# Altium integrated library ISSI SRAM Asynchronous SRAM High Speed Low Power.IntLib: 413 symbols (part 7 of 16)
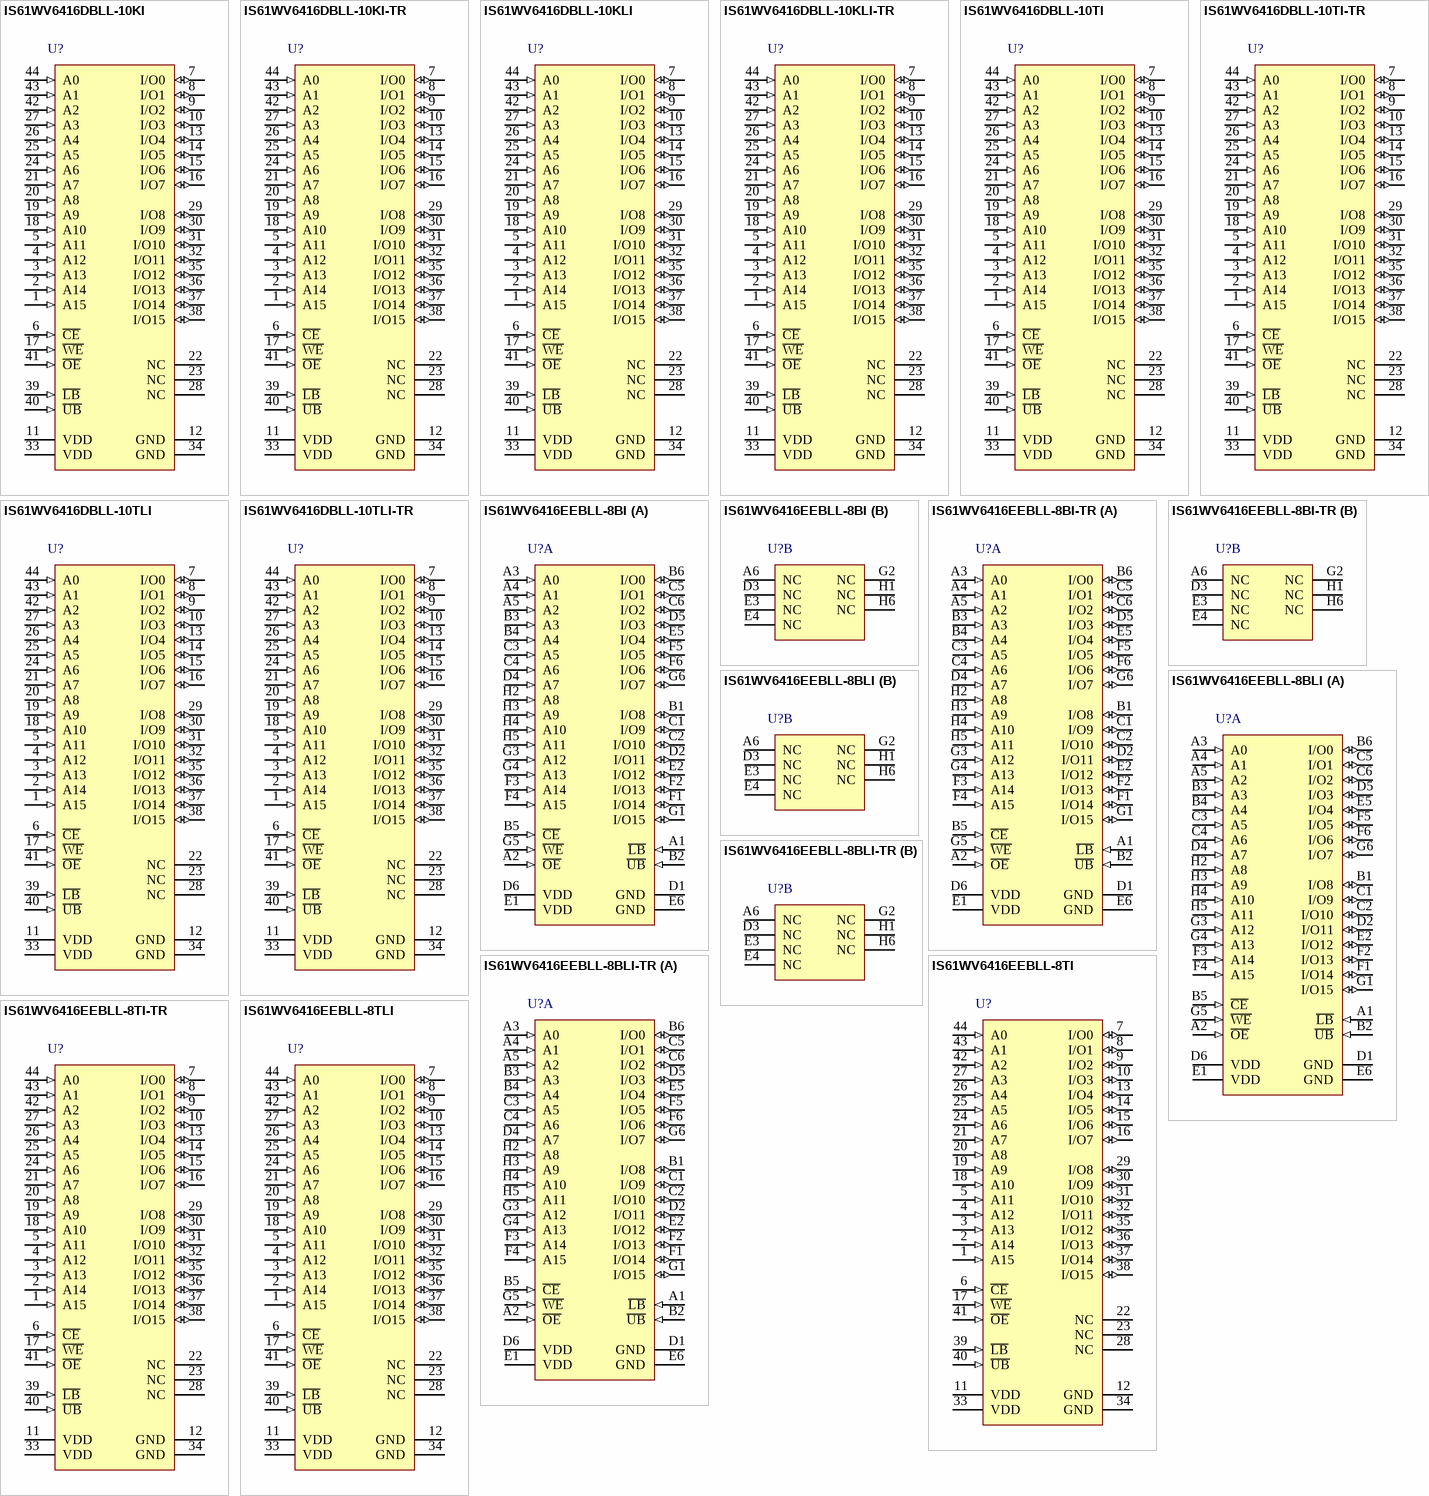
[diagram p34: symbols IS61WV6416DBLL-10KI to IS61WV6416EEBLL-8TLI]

## IS61WV6416EEBLL-8TLI
designator U?
1 M High Speed Asynchronous CMOS SRAM with ECC, 64 K x 16, -40 to 85 degC, 44-Pin SOP (TSOP-2-44), Pb-Free; Manufacturer: Integrated Silicon Solution Inc (ISSI); PartNumber: IS61WV6416EEBLL-8TLI; Density: 1M; Organization: 64K x 16; Packing: Tray / Tube; Speed (ns): 8
footprint ISSI-TSOP-2-44_N (SOP, 44-Leads, Body 18.5x10.3mm, Pitch 0.8mm, IPC Medium Density)
pins: 1 A15 (in) "Address Inputs", 2 A14 (in) "Address Inputs", 3 A13 (in) "Address Inputs", 4 A12 (in) "Address Inputs", 5 A11 (in) "Address Inputs", 6 ~{CE} (in) "Chip Enable Input", 7 I/O0 (io) "Data Inputs/Outputs", 8 I/O1 (io) "Data Inputs/Outputs", 9 I/O2 (io) "Data Inputs/Outputs", 10 I/O3 (io) "Data Inputs/Outputs", 11 VDD (power) "Power", 12 GND (power) "Ground", 13 I/O4 (io) "Data Inputs/Outputs", 14 I/O5 (io) "Data Inputs/Outputs", 15 I/O6 (io) "Data Inputs/Outputs", 16 I/O7 (io) "Data Inputs/Outputs", 17 ~{WE} (in) "Write Enable Input", 18 A10 (in) "Address Inputs", 19 A9 (in) "Address Inputs", 20 A8 (in) "Address Inputs", 21 A7 (in) "Address Inputs", 22 NC "No Connection", 23 NC "No Connection", 24 A6 (in) "Address Inputs", 25 A5 (in) "Address Inputs", 26 A4 (in) "Address Inputs", 27 A3 (in) "Address Inputs", 28 NC "No Connection", 29 I/O8 (io) "Data Inputs/Outputs", 30 I/O9 (io) "Data Inputs/Outputs", 31 I/O10 (io) "Data Inputs/Outputs", 32 I/O11 (io) "Data Inputs/Outputs", 33 VDD (power) "Power", 34 GND (power) "Ground", 35 I/O12 (io) "Data Inputs/Outputs", 36 I/O13 (io) "Data Inputs/Outputs", 37 I/O14 (io) "Data Inputs/Outputs", 38 I/O15 (io) "Data Inputs/Outputs", 39 ~{LB} (in) "Lower-byte Control (I/O0-I/O7)", 40 ~{UB} (in) "Upper-byte Control (I/O8-I/O15)", 41 ~{OE} (in) "Output Enable Input", 42 A2 (in) "Address Inputs", 43 A1 (in) "Address Inputs", 44 A0 (in) "Address Inputs"

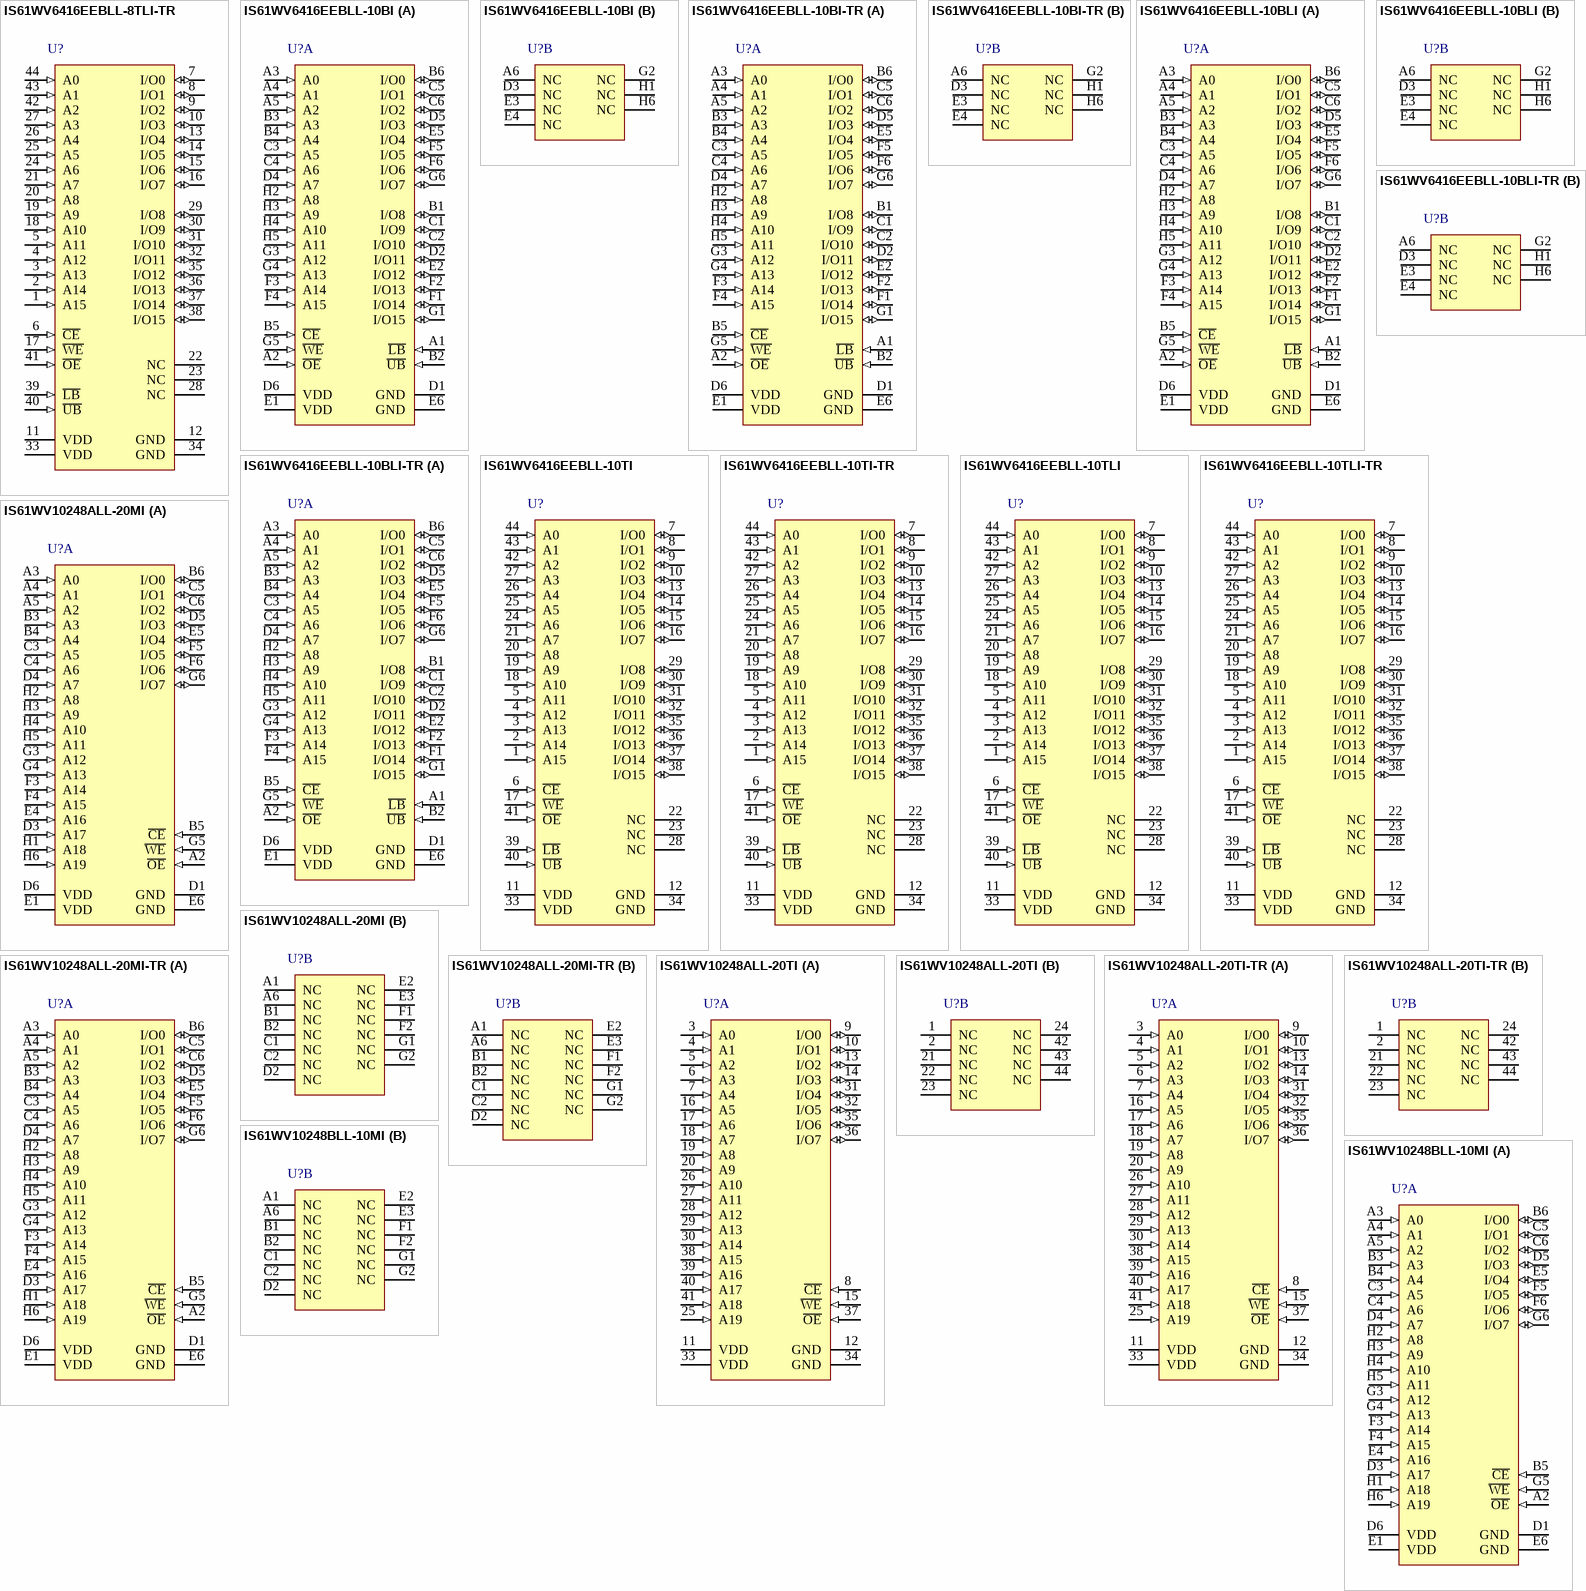
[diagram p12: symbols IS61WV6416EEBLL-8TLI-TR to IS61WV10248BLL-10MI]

## IS61WV6416EEBLL-8TLI-TR
designator U?
1 M High Speed Asynchronous CMOS SRAM with ECC, 64 K x 16, -40 to 85 degC, 44-Pin SOP (TSOP-2-44), Pb-Free; Manufacturer: Integrated Silicon Solution Inc (ISSI); PartNumber: IS61WV6416EEBLL-8TLI-TR; Density: 1M; Organization: 64K x 16; Packing: Tape & Reel; Speed (ns): 8
footprint ISSI-TSOP-2-44_N (SOP, 44-Leads, Body 18.5x10.3mm, Pitch 0.8mm, IPC Medium Density)
pins: 1 A15 (in) "Address Inputs", 2 A14 (in) "Address Inputs", 3 A13 (in) "Address Inputs", 4 A12 (in) "Address Inputs", 5 A11 (in) "Address Inputs", 6 ~{CE} (in) "Chip Enable Input", 7 I/O0 (io) "Data Inputs/Outputs", 8 I/O1 (io) "Data Inputs/Outputs", 9 I/O2 (io) "Data Inputs/Outputs", 10 I/O3 (io) "Data Inputs/Outputs", 11 VDD (power) "Power", 12 GND (power) "Ground", 13 I/O4 (io) "Data Inputs/Outputs", 14 I/O5 (io) "Data Inputs/Outputs", 15 I/O6 (io) "Data Inputs/Outputs", 16 I/O7 (io) "Data Inputs/Outputs", 17 ~{WE} (in) "Write Enable Input", 18 A10 (in) "Address Inputs", 19 A9 (in) "Address Inputs", 20 A8 (in) "Address Inputs", 21 A7 (in) "Address Inputs", 22 NC "No Connection", 23 NC "No Connection", 24 A6 (in) "Address Inputs", 25 A5 (in) "Address Inputs", 26 A4 (in) "Address Inputs", 27 A3 (in) "Address Inputs", 28 NC "No Connection", 29 I/O8 (io) "Data Inputs/Outputs", 30 I/O9 (io) "Data Inputs/Outputs", 31 I/O10 (io) "Data Inputs/Outputs", 32 I/O11 (io) "Data Inputs/Outputs", 33 VDD (power) "Power", 34 GND (power) "Ground", 35 I/O12 (io) "Data Inputs/Outputs", 36 I/O13 (io) "Data Inputs/Outputs", 37 I/O14 (io) "Data Inputs/Outputs", 38 I/O15 (io) "Data Inputs/Outputs", 39 ~{LB} (in) "Lower-byte Control (I/O0-I/O7)", 40 ~{UB} (in) "Upper-byte Control (I/O8-I/O15)", 41 ~{OE} (in) "Output Enable Input", 42 A2 (in) "Address Inputs", 43 A1 (in) "Address Inputs", 44 A0 (in) "Address Inputs"

## IS61WV6416EEBLL-10BI
designator U?
1 M High Speed Asynchronous CMOS SRAM with ECC, 64 K x 16, -40 to 85 degC, 48-Pin BGA (TF-BGA-48); Manufacturer: Integrated Silicon Solution Inc (ISSI); PartNumber: IS61WV6416EEBLL-10BI; Density: 1M; Organization: 64K x 16; Packing: Tray / Tube; Speed (ns): 10
footprint ISSI-TF-BGA-48-6000X8000DE (BGA, 48-Balls, Body 8x6mm, Pitch 0.75mm)
part A pins: A1 ~{LB} (in) "Lower-byte Control (I/O0-I/O7)", A2 ~{OE} (in) "Output Enable Input", A3 A0 (in) "Address Input", A4 A1 (in) "Address Input", A5 A2 (in) "Address Input", B1 I/O8 (io) "Data Input/Output", B2 ~{UB} (in) "Upper-byte Control (I/O8-I/O15)", B3 A3 (in) "Address Input", B4 A4 (in) "Address Input", B5 ~{CE} (in) "Chip Enable Input", B6 I/O0 (io) "Data Input/Output", C1 I/O9 (io) "Data Input/Output", C2 I/O10 (io) "Data Input/Output", C3 A5 (in) "Address Input", C4 A6 (in) "Address Input", C5 I/O1 (io) "Data Input/Output", C6 I/O2 (io) "Data Input/Output", D1 GND (power) "Ground", D2 I/O11 (io) "Data Input/Output", D4 A7 (in) "Address Input", D5 I/O3 (io) "Data Input/Output", D6 VDD (power) "Power", E1 VDD (power) "Power", E2 I/O12 (io) "Data Input/Output", E5 I/O4 (io) "Data Input/Output", E6 GND (power) "Ground", F1 I/O14 (io) "Data Input/Output", F2 I/O13 (io) "Data Input/Output", F3 A14 (in) "Address Input", F4 A15 (in) "Address Input", F5 I/O5 (io) "Data Input/Output", F6 I/O6 (io) "Data Input/Output", G1 I/O15 (io) "Data Input/Output", G3 A12 (in) "Address Input", G4 A13 (in) "Address Input", G5 ~{WE} (in) "Write Enable Input", G6 I/O7 (io) "Data Input/Output", H2 A8 (in) "Address Input", H3 A9 (in) "Address Input", H4 A10 (in) "Address Input", H5 A11 (in) "Address Input"
part B pins: A6 NC "No Connection", D3 NC "No Connection", E3 NC "No Connection", E4 NC "No Connection", G2 NC "No Connection", H1 NC "No Connection", H6 NC "No Connection"

## IS61WV6416EEBLL-10BI-TR
designator U?
1 M High Speed Asynchronous CMOS SRAM with ECC, 64 K x 16, -40 to 85 degC, 48-Pin BGA (TF-BGA-48); Manufacturer: Integrated Silicon Solution Inc (ISSI); PartNumber: IS61WV6416EEBLL-10BI-TR; Density: 1M; Organization: 64K x 16; Packing: Tape & Reel; Speed (ns): 10
footprint ISSI-TF-BGA-48-6000X8000DE (BGA, 48-Balls, Body 8x6mm, Pitch 0.75mm)
part A pins: A1 ~{LB} (in) "Lower-byte Control (I/O0-I/O7)", A2 ~{OE} (in) "Output Enable Input", A3 A0 (in) "Address Input", A4 A1 (in) "Address Input", A5 A2 (in) "Address Input", B1 I/O8 (io) "Data Input/Output", B2 ~{UB} (in) "Upper-byte Control (I/O8-I/O15)", B3 A3 (in) "Address Input", B4 A4 (in) "Address Input", B5 ~{CE} (in) "Chip Enable Input", B6 I/O0 (io) "Data Input/Output", C1 I/O9 (io) "Data Input/Output", C2 I/O10 (io) "Data Input/Output", C3 A5 (in) "Address Input", C4 A6 (in) "Address Input", C5 I/O1 (io) "Data Input/Output", C6 I/O2 (io) "Data Input/Output", D1 GND (power) "Ground", D2 I/O11 (io) "Data Input/Output", D4 A7 (in) "Address Input", D5 I/O3 (io) "Data Input/Output", D6 VDD (power) "Power", E1 VDD (power) "Power", E2 I/O12 (io) "Data Input/Output", E5 I/O4 (io) "Data Input/Output", E6 GND (power) "Ground", F1 I/O14 (io) "Data Input/Output", F2 I/O13 (io) "Data Input/Output", F3 A14 (in) "Address Input", F4 A15 (in) "Address Input", F5 I/O5 (io) "Data Input/Output", F6 I/O6 (io) "Data Input/Output", G1 I/O15 (io) "Data Input/Output", G3 A12 (in) "Address Input", G4 A13 (in) "Address Input", G5 ~{WE} (in) "Write Enable Input", G6 I/O7 (io) "Data Input/Output", H2 A8 (in) "Address Input", H3 A9 (in) "Address Input", H4 A10 (in) "Address Input", H5 A11 (in) "Address Input"
part B pins: A6 NC "No Connection", D3 NC "No Connection", E3 NC "No Connection", E4 NC "No Connection", G2 NC "No Connection", H1 NC "No Connection", H6 NC "No Connection"

## IS61WV6416EEBLL-10BLI
designator U?
1 M High Speed Asynchronous CMOS SRAM with ECC, 64 K x 16, -40 to 85 degC, 48-Pin BGA (TF-BGA-48), Pb-Free; Manufacturer: Integrated Silicon Solution Inc (ISSI); PartNumber: IS61WV6416EEBLL-10BLI; Density: 1M; Organization: 64K x 16; Packing: Tray / Tube; Speed (ns): 10
footprint ISSI-TF-BGA-48-6000X8000DE (BGA, 48-Balls, Body 8x6mm, Pitch 0.75mm)
part A pins: A1 ~{LB} (in) "Lower-byte Control (I/O0-I/O7)", A2 ~{OE} (in) "Output Enable Input", A3 A0 (in) "Address Input", A4 A1 (in) "Address Input", A5 A2 (in) "Address Input", B1 I/O8 (io) "Data Input/Output", B2 ~{UB} (in) "Upper-byte Control (I/O8-I/O15)", B3 A3 (in) "Address Input", B4 A4 (in) "Address Input", B5 ~{CE} (in) "Chip Enable Input", B6 I/O0 (io) "Data Input/Output", C1 I/O9 (io) "Data Input/Output", C2 I/O10 (io) "Data Input/Output", C3 A5 (in) "Address Input", C4 A6 (in) "Address Input", C5 I/O1 (io) "Data Input/Output", C6 I/O2 (io) "Data Input/Output", D1 GND (power) "Ground", D2 I/O11 (io) "Data Input/Output", D4 A7 (in) "Address Input", D5 I/O3 (io) "Data Input/Output", D6 VDD (power) "Power", E1 VDD (power) "Power", E2 I/O12 (io) "Data Input/Output", E5 I/O4 (io) "Data Input/Output", E6 GND (power) "Ground", F1 I/O14 (io) "Data Input/Output", F2 I/O13 (io) "Data Input/Output", F3 A14 (in) "Address Input", F4 A15 (in) "Address Input", F5 I/O5 (io) "Data Input/Output", F6 I/O6 (io) "Data Input/Output", G1 I/O15 (io) "Data Input/Output", G3 A12 (in) "Address Input", G4 A13 (in) "Address Input", G5 ~{WE} (in) "Write Enable Input", G6 I/O7 (io) "Data Input/Output", H2 A8 (in) "Address Input", H3 A9 (in) "Address Input", H4 A10 (in) "Address Input", H5 A11 (in) "Address Input"
part B pins: A6 NC "No Connection", D3 NC "No Connection", E3 NC "No Connection", E4 NC "No Connection", G2 NC "No Connection", H1 NC "No Connection", H6 NC "No Connection"

## IS61WV6416EEBLL-10BLI-TR
designator U?
1 M High Speed Asynchronous CMOS SRAM with ECC, 64 K x 16, -40 to 85 degC, 48-Pin BGA (TF-BGA-48), Pb-Free; Manufacturer: Integrated Silicon Solution Inc (ISSI); PartNumber: IS61WV6416EEBLL-10BLI-TR; Density: 1M; Organization: 64K x 16; Packing: Tape & Reel; Speed (ns): 10
footprint ISSI-TF-BGA-48-6000X8000DE (BGA, 48-Balls, Body 8x6mm, Pitch 0.75mm)
part A pins: A1 ~{LB} (in) "Lower-byte Control (I/O0-I/O7)", A2 ~{OE} (in) "Output Enable Input", A3 A0 (in) "Address Input", A4 A1 (in) "Address Input", A5 A2 (in) "Address Input", B1 I/O8 (io) "Data Input/Output", B2 ~{UB} (in) "Upper-byte Control (I/O8-I/O15)", B3 A3 (in) "Address Input", B4 A4 (in) "Address Input", B5 ~{CE} (in) "Chip Enable Input", B6 I/O0 (io) "Data Input/Output", C1 I/O9 (io) "Data Input/Output", C2 I/O10 (io) "Data Input/Output", C3 A5 (in) "Address Input", C4 A6 (in) "Address Input", C5 I/O1 (io) "Data Input/Output", C6 I/O2 (io) "Data Input/Output", D1 GND (power) "Ground", D2 I/O11 (io) "Data Input/Output", D4 A7 (in) "Address Input", D5 I/O3 (io) "Data Input/Output", D6 VDD (power) "Power", E1 VDD (power) "Power", E2 I/O12 (io) "Data Input/Output", E5 I/O4 (io) "Data Input/Output", E6 GND (power) "Ground", F1 I/O14 (io) "Data Input/Output", F2 I/O13 (io) "Data Input/Output", F3 A14 (in) "Address Input", F4 A15 (in) "Address Input", F5 I/O5 (io) "Data Input/Output", F6 I/O6 (io) "Data Input/Output", G1 I/O15 (io) "Data Input/Output", G3 A12 (in) "Address Input", G4 A13 (in) "Address Input", G5 ~{WE} (in) "Write Enable Input", G6 I/O7 (io) "Data Input/Output", H2 A8 (in) "Address Input", H3 A9 (in) "Address Input", H4 A10 (in) "Address Input", H5 A11 (in) "Address Input"
part B pins: A6 NC "No Connection", D3 NC "No Connection", E3 NC "No Connection", E4 NC "No Connection", G2 NC "No Connection", H1 NC "No Connection", H6 NC "No Connection"

## IS61WV6416EEBLL-10TI
designator U?
1 M High Speed Asynchronous CMOS SRAM with ECC, 64 K x 16, -40 to 85 degC, 44-Pin SOP (TSOP-2-44); Manufacturer: Integrated Silicon Solution Inc (ISSI); PartNumber: IS61WV6416EEBLL-10TI; Density: 1M; Organization: 64K x 16; Packing: Tray / Tube; Speed (ns): 10
footprint ISSI-TSOP-2-44_N (SOP, 44-Leads, Body 18.5x10.3mm, Pitch 0.8mm, IPC Medium Density)
pins: 1 A15 (in) "Address Inputs", 2 A14 (in) "Address Inputs", 3 A13 (in) "Address Inputs", 4 A12 (in) "Address Inputs", 5 A11 (in) "Address Inputs", 6 ~{CE} (in) "Chip Enable Input", 7 I/O0 (io) "Data Inputs/Outputs", 8 I/O1 (io) "Data Inputs/Outputs", 9 I/O2 (io) "Data Inputs/Outputs", 10 I/O3 (io) "Data Inputs/Outputs", 11 VDD (power) "Power", 12 GND (power) "Ground", 13 I/O4 (io) "Data Inputs/Outputs", 14 I/O5 (io) "Data Inputs/Outputs", 15 I/O6 (io) "Data Inputs/Outputs", 16 I/O7 (io) "Data Inputs/Outputs", 17 ~{WE} (in) "Write Enable Input", 18 A10 (in) "Address Inputs", 19 A9 (in) "Address Inputs", 20 A8 (in) "Address Inputs", 21 A7 (in) "Address Inputs", 22 NC "No Connection", 23 NC "No Connection", 24 A6 (in) "Address Inputs", 25 A5 (in) "Address Inputs", 26 A4 (in) "Address Inputs", 27 A3 (in) "Address Inputs", 28 NC "No Connection", 29 I/O8 (io) "Data Inputs/Outputs", 30 I/O9 (io) "Data Inputs/Outputs", 31 I/O10 (io) "Data Inputs/Outputs", 32 I/O11 (io) "Data Inputs/Outputs", 33 VDD (power) "Power", 34 GND (power) "Ground", 35 I/O12 (io) "Data Inputs/Outputs", 36 I/O13 (io) "Data Inputs/Outputs", 37 I/O14 (io) "Data Inputs/Outputs", 38 I/O15 (io) "Data Inputs/Outputs", 39 ~{LB} (in) "Lower-byte Control (I/O0-I/O7)", 40 ~{UB} (in) "Upper-byte Control (I/O8-I/O15)", 41 ~{OE} (in) "Output Enable Input", 42 A2 (in) "Address Inputs", 43 A1 (in) "Address Inputs", 44 A0 (in) "Address Inputs"

## IS61WV6416EEBLL-10TI-TR
designator U?
1 M High Speed Asynchronous CMOS SRAM with ECC, 64 K x 16, -40 to 85 degC, 44-Pin SOP (TSOP-2-44); Manufacturer: Integrated Silicon Solution Inc (ISSI); PartNumber: IS61WV6416EEBLL-10TI-TR; Density: 1M; Organization: 64K x 16; Packing: Tape & Reel; Speed (ns): 10
footprint ISSI-TSOP-2-44_N (SOP, 44-Leads, Body 18.5x10.3mm, Pitch 0.8mm, IPC Medium Density)
pins: 1 A15 (in) "Address Inputs", 2 A14 (in) "Address Inputs", 3 A13 (in) "Address Inputs", 4 A12 (in) "Address Inputs", 5 A11 (in) "Address Inputs", 6 ~{CE} (in) "Chip Enable Input", 7 I/O0 (io) "Data Inputs/Outputs", 8 I/O1 (io) "Data Inputs/Outputs", 9 I/O2 (io) "Data Inputs/Outputs", 10 I/O3 (io) "Data Inputs/Outputs", 11 VDD (power) "Power", 12 GND (power) "Ground", 13 I/O4 (io) "Data Inputs/Outputs", 14 I/O5 (io) "Data Inputs/Outputs", 15 I/O6 (io) "Data Inputs/Outputs", 16 I/O7 (io) "Data Inputs/Outputs", 17 ~{WE} (in) "Write Enable Input", 18 A10 (in) "Address Inputs", 19 A9 (in) "Address Inputs", 20 A8 (in) "Address Inputs", 21 A7 (in) "Address Inputs", 22 NC "No Connection", 23 NC "No Connection", 24 A6 (in) "Address Inputs", 25 A5 (in) "Address Inputs", 26 A4 (in) "Address Inputs", 27 A3 (in) "Address Inputs", 28 NC "No Connection", 29 I/O8 (io) "Data Inputs/Outputs", 30 I/O9 (io) "Data Inputs/Outputs", 31 I/O10 (io) "Data Inputs/Outputs", 32 I/O11 (io) "Data Inputs/Outputs", 33 VDD (power) "Power", 34 GND (power) "Ground", 35 I/O12 (io) "Data Inputs/Outputs", 36 I/O13 (io) "Data Inputs/Outputs", 37 I/O14 (io) "Data Inputs/Outputs", 38 I/O15 (io) "Data Inputs/Outputs", 39 ~{LB} (in) "Lower-byte Control (I/O0-I/O7)", 40 ~{UB} (in) "Upper-byte Control (I/O8-I/O15)", 41 ~{OE} (in) "Output Enable Input", 42 A2 (in) "Address Inputs", 43 A1 (in) "Address Inputs", 44 A0 (in) "Address Inputs"

## IS61WV6416EEBLL-10TLI
designator U?
1 M High Speed Asynchronous CMOS SRAM with ECC, 64 K x 16, -40 to 85 degC, 44-Pin SOP (TSOP-2-44), Pb-Free; Manufacturer: Integrated Silicon Solution Inc (ISSI); PartNumber: IS61WV6416EEBLL-10TLI; Density: 1M; Organization: 64K x 16; Packing: Tray / Tube; Speed (ns): 10
footprint ISSI-TSOP-2-44_N (SOP, 44-Leads, Body 18.5x10.3mm, Pitch 0.8mm, IPC Medium Density)
pins: 1 A15 (in) "Address Inputs", 2 A14 (in) "Address Inputs", 3 A13 (in) "Address Inputs", 4 A12 (in) "Address Inputs", 5 A11 (in) "Address Inputs", 6 ~{CE} (in) "Chip Enable Input", 7 I/O0 (io) "Data Inputs/Outputs", 8 I/O1 (io) "Data Inputs/Outputs", 9 I/O2 (io) "Data Inputs/Outputs", 10 I/O3 (io) "Data Inputs/Outputs", 11 VDD (power) "Power", 12 GND (power) "Ground", 13 I/O4 (io) "Data Inputs/Outputs", 14 I/O5 (io) "Data Inputs/Outputs", 15 I/O6 (io) "Data Inputs/Outputs", 16 I/O7 (io) "Data Inputs/Outputs", 17 ~{WE} (in) "Write Enable Input", 18 A10 (in) "Address Inputs", 19 A9 (in) "Address Inputs", 20 A8 (in) "Address Inputs", 21 A7 (in) "Address Inputs", 22 NC "No Connection", 23 NC "No Connection", 24 A6 (in) "Address Inputs", 25 A5 (in) "Address Inputs", 26 A4 (in) "Address Inputs", 27 A3 (in) "Address Inputs", 28 NC "No Connection", 29 I/O8 (io) "Data Inputs/Outputs", 30 I/O9 (io) "Data Inputs/Outputs", 31 I/O10 (io) "Data Inputs/Outputs", 32 I/O11 (io) "Data Inputs/Outputs", 33 VDD (power) "Power", 34 GND (power) "Ground", 35 I/O12 (io) "Data Inputs/Outputs", 36 I/O13 (io) "Data Inputs/Outputs", 37 I/O14 (io) "Data Inputs/Outputs", 38 I/O15 (io) "Data Inputs/Outputs", 39 ~{LB} (in) "Lower-byte Control (I/O0-I/O7)", 40 ~{UB} (in) "Upper-byte Control (I/O8-I/O15)", 41 ~{OE} (in) "Output Enable Input", 42 A2 (in) "Address Inputs", 43 A1 (in) "Address Inputs", 44 A0 (in) "Address Inputs"

## IS61WV6416EEBLL-10TLI-TR
designator U?
1 M High Speed Asynchronous CMOS SRAM with ECC, 64 K x 16, -40 to 85 degC, 44-Pin SOP (TSOP-2-44), Pb-Free; Manufacturer: Integrated Silicon Solution Inc (ISSI); PartNumber: IS61WV6416EEBLL-10TLI-TR; Density: 1M; Organization: 64K x 16; Packing: Tape & Reel; Speed (ns): 10
footprint ISSI-TSOP-2-44_N (SOP, 44-Leads, Body 18.5x10.3mm, Pitch 0.8mm, IPC Medium Density)
pins: 1 A15 (in) "Address Inputs", 2 A14 (in) "Address Inputs", 3 A13 (in) "Address Inputs", 4 A12 (in) "Address Inputs", 5 A11 (in) "Address Inputs", 6 ~{CE} (in) "Chip Enable Input", 7 I/O0 (io) "Data Inputs/Outputs", 8 I/O1 (io) "Data Inputs/Outputs", 9 I/O2 (io) "Data Inputs/Outputs", 10 I/O3 (io) "Data Inputs/Outputs", 11 VDD (power) "Power", 12 GND (power) "Ground", 13 I/O4 (io) "Data Inputs/Outputs", 14 I/O5 (io) "Data Inputs/Outputs", 15 I/O6 (io) "Data Inputs/Outputs", 16 I/O7 (io) "Data Inputs/Outputs", 17 ~{WE} (in) "Write Enable Input", 18 A10 (in) "Address Inputs", 19 A9 (in) "Address Inputs", 20 A8 (in) "Address Inputs", 21 A7 (in) "Address Inputs", 22 NC "No Connection", 23 NC "No Connection", 24 A6 (in) "Address Inputs", 25 A5 (in) "Address Inputs", 26 A4 (in) "Address Inputs", 27 A3 (in) "Address Inputs", 28 NC "No Connection", 29 I/O8 (io) "Data Inputs/Outputs", 30 I/O9 (io) "Data Inputs/Outputs", 31 I/O10 (io) "Data Inputs/Outputs", 32 I/O11 (io) "Data Inputs/Outputs", 33 VDD (power) "Power", 34 GND (power) "Ground", 35 I/O12 (io) "Data Inputs/Outputs", 36 I/O13 (io) "Data Inputs/Outputs", 37 I/O14 (io) "Data Inputs/Outputs", 38 I/O15 (io) "Data Inputs/Outputs", 39 ~{LB} (in) "Lower-byte Control (I/O0-I/O7)", 40 ~{UB} (in) "Upper-byte Control (I/O8-I/O15)", 41 ~{OE} (in) "Output Enable Input", 42 A2 (in) "Address Inputs", 43 A1 (in) "Address Inputs", 44 A0 (in) "Address Inputs"

## IS61WV10248ALL-20MI
designator U?
8 M High Speed CMOS SRAM, 1 M x 8, -40 to 85 degC, 48-Pin BGA (TF-BGA-48); Manufacturer: Integrated Silicon Solution Inc (ISSI); PartNumber: IS61WV10248ALL-20MI; Organization: 1M x 8; Packing: Tray / Tube; Speed (ns): 20
footprint ISSI-TF-BGA-48-9000x11000DE (BGA, 48-Balls, Body 11x9mm, Pitch 0.75mm)
part A pins: A2 ~{OE} (in) "Output Enable Input", A3 A0 (in) "Address Input", A4 A1 (in) "Address Input", A5 A2 (in) "Address Input", B3 A3 (in) "Address Input", B4 A4 (in) "Address Input", B5 ~{CE} (in) "Chip Enable Input", B6 I/O0 (io) "Data Input / Output", C3 A5 (in) "Address Input", C4 A6 (in) "Address Input", C5 I/O1 (io) "Data Input / Output", C6 I/O2 (io) "Data Input / Output", D1 GND (power) "Ground", D3 A17 (in) "Address Input", D4 A7 (in) "Address Input", D5 I/O3 (io) "Data Input / Output", D6 VDD (power) "Power", E1 VDD (power) "Power", E4 A16 (in) "Address Input", E5 I/O4 (io) "Data Input / Output", E6 GND (power) "Ground", F3 A14 (in) "Address Input", F4 A15 (in) "Address Input", F5 I/O5 (io) "Data Input / Output", F6 I/O6 (io) "Data Input / Output", G3 A12 (in) "Address Input", G4 A13 (in) "Address Input", G5 ~{WE} (in) "Write Enable Input", G6 I/O7 (io) "Data Input / Output", H1 A18 (in) "Address Input", H2 A8 (in) "Address Input", H3 A9 (in) "Address Input", H4 A10 (in) "Address Input", H5 A11 (in) "Address Input", H6 A19 (in) "Address Input"
part B pins: A1 NC "No Connection", A6 NC "No Connection", B1 NC "No Connection", B2 NC "No Connection", C1 NC "No Connection", C2 NC "No Connection", D2 NC "No Connection", E2 NC "No Connection", E3 NC "No Connection", F1 NC "No Connection", F2 NC "No Connection", G1 NC "No Connection", G2 NC "No Connection"

## IS61WV10248ALL-20MI-TR
designator U?
8 M High Speed CMOS SRAM, 1 M x 8, -40 to 85 degC, 48-Pin BGA (TF-BGA-48); Manufacturer: Integrated Silicon Solution Inc (ISSI); PartNumber: IS61WV10248ALL-20MI-TR; Organization: 1M x 8; Packing: Tape & Reel; Speed (ns): 20
footprint ISSI-TF-BGA-48-9000x11000DE (BGA, 48-Balls, Body 11x9mm, Pitch 0.75mm)
part A pins: A2 ~{OE} (in) "Output Enable Input", A3 A0 (in) "Address Input", A4 A1 (in) "Address Input", A5 A2 (in) "Address Input", B3 A3 (in) "Address Input", B4 A4 (in) "Address Input", B5 ~{CE} (in) "Chip Enable Input", B6 I/O0 (io) "Data Input / Output", C3 A5 (in) "Address Input", C4 A6 (in) "Address Input", C5 I/O1 (io) "Data Input / Output", C6 I/O2 (io) "Data Input / Output", D1 GND (power) "Ground", D3 A17 (in) "Address Input", D4 A7 (in) "Address Input", D5 I/O3 (io) "Data Input / Output", D6 VDD (power) "Power", E1 VDD (power) "Power", E4 A16 (in) "Address Input", E5 I/O4 (io) "Data Input / Output", E6 GND (power) "Ground", F3 A14 (in) "Address Input", F4 A15 (in) "Address Input", F5 I/O5 (io) "Data Input / Output", F6 I/O6 (io) "Data Input / Output", G3 A12 (in) "Address Input", G4 A13 (in) "Address Input", G5 ~{WE} (in) "Write Enable Input", G6 I/O7 (io) "Data Input / Output", H1 A18 (in) "Address Input", H2 A8 (in) "Address Input", H3 A9 (in) "Address Input", H4 A10 (in) "Address Input", H5 A11 (in) "Address Input", H6 A19 (in) "Address Input"
part B pins: A1 NC "No Connection", A6 NC "No Connection", B1 NC "No Connection", B2 NC "No Connection", C1 NC "No Connection", C2 NC "No Connection", D2 NC "No Connection", E2 NC "No Connection", E3 NC "No Connection", F1 NC "No Connection", F2 NC "No Connection", G1 NC "No Connection", G2 NC "No Connection"

## IS61WV10248ALL-20TI
designator U?
8 M High Speed CMOS SRAM, 1 M x 8, -40 to 85 degC, 44-Pin SOP (TSOP-2-44); Manufacturer: Integrated Silicon Solution Inc (ISSI); PartNumber: IS61WV10248ALL-20TI; Organization: 1M x 8; Packing: Tray / Tube; Speed (ns): 20
footprint ISSI-TSOP-2-44_N (SOP, 44-Leads, Body 18.5x10.3mm, Pitch 0.8mm, IPC Medium Density)
part A pins: 3 A0 (in) "Address Input", 4 A1 (in) "Address Input", 5 A2 (in) "Address Input", 6 A3 (in) "Address Input", 7 A4 (in) "Address Input", 8 ~{CE} (in) "Chip Enable Input", 9 I/O0 (io) "Data Input / Output", 10 I/O1 (io) "Data Input / Output", 11 VDD (power) "Power", 12 GND (power) "Ground", 13 I/O2 (io) "Data Input / Output", 14 I/O3 (io) "Data Input / Output", 15 ~{WE} (in) "Write Enable Input", 16 A5 (in) "Address Input", 17 A6 (in) "Address Input", 18 A7 (in) "Address Input", 19 A8 (in) "Address Input", 20 A9 (in) "Address Input", 25 A19 (in) "Address Input", 26 A10 (in) "Address Input", 27 A11 (in) "Address Input", 28 A12 (in) "Address Input", 29 A13 (in) "Address Input", 30 A14 (in) "Address Input", 31 I/O4 (io) "Data Input / Output", 32 I/O5 (io) "Data Input / Output", 33 VDD (power) "Power", 34 GND (power) "Ground", 35 I/O6 (io) "Data Input / Output", 36 I/O7 (io) "Data Input / Output", 37 ~{OE} (in) "Output Enable Input", 38 A15 (in) "Address Input", 39 A16 (in) "Address Input", 40 A17 (in) "Address Input", 41 A18 (in) "Address Input"
part B pins: 1 NC "No Connection", 2 NC "No Connection", 21 NC "No Connection", 22 NC "No Connection", 23 NC "No Connection", 24 NC "No Connection", 42 NC "No Connection", 43 NC "No Connection", 44 NC "No Connection"

## IS61WV10248ALL-20TI-TR
designator U?
8 M High Speed CMOS SRAM, 1 M x 8, -40 to 85 degC, 44-Pin SOP (TSOP-2-44); Manufacturer: Integrated Silicon Solution Inc (ISSI); PartNumber: IS61WV10248ALL-20TI-TR; Organization: 1M x 8; Packing: Tape & Reel; Speed (ns): 20
footprint ISSI-TSOP-2-44_N (SOP, 44-Leads, Body 18.5x10.3mm, Pitch 0.8mm, IPC Medium Density)
part A pins: 3 A0 (in) "Address Input", 4 A1 (in) "Address Input", 5 A2 (in) "Address Input", 6 A3 (in) "Address Input", 7 A4 (in) "Address Input", 8 ~{CE} (in) "Chip Enable Input", 9 I/O0 (io) "Data Input / Output", 10 I/O1 (io) "Data Input / Output", 11 VDD (power) "Power", 12 GND (power) "Ground", 13 I/O2 (io) "Data Input / Output", 14 I/O3 (io) "Data Input / Output", 15 ~{WE} (in) "Write Enable Input", 16 A5 (in) "Address Input", 17 A6 (in) "Address Input", 18 A7 (in) "Address Input", 19 A8 (in) "Address Input", 20 A9 (in) "Address Input", 25 A19 (in) "Address Input", 26 A10 (in) "Address Input", 27 A11 (in) "Address Input", 28 A12 (in) "Address Input", 29 A13 (in) "Address Input", 30 A14 (in) "Address Input", 31 I/O4 (io) "Data Input / Output", 32 I/O5 (io) "Data Input / Output", 33 VDD (power) "Power", 34 GND (power) "Ground", 35 I/O6 (io) "Data Input / Output", 36 I/O7 (io) "Data Input / Output", 37 ~{OE} (in) "Output Enable Input", 38 A15 (in) "Address Input", 39 A16 (in) "Address Input", 40 A17 (in) "Address Input", 41 A18 (in) "Address Input"
part B pins: 1 NC "No Connection", 2 NC "No Connection", 21 NC "No Connection", 22 NC "No Connection", 23 NC "No Connection", 24 NC "No Connection", 42 NC "No Connection", 43 NC "No Connection", 44 NC "No Connection"

## IS61WV10248BLL-10MI
designator U?
8 M High Speed CMOS SRAM, 1 M x 8, -40 to 85 degC, 48-Pin BGA (TF-BGA-48); Manufacturer: Integrated Silicon Solution Inc (ISSI); PartNumber: IS61WV10248BLL-10MI; Organization: 1M x 8; Packing: Tray / Tube; Speed (ns): 10
footprint ISSI-TF-BGA-48-9000x11000DE (BGA, 48-Balls, Body 11x9mm, Pitch 0.75mm)
part A pins: A2 ~{OE} (in) "Output Enable Input", A3 A0 (in) "Address Input", A4 A1 (in) "Address Input", A5 A2 (in) "Address Input", B3 A3 (in) "Address Input", B4 A4 (in) "Address Input", B5 ~{CE} (in) "Chip Enable Input", B6 I/O0 (io) "Data Input / Output", C3 A5 (in) "Address Input", C4 A6 (in) "Address Input", C5 I/O1 (io) "Data Input / Output", C6 I/O2 (io) "Data Input / Output", D1 GND (power) "Ground", D3 A17 (in) "Address Input", D4 A7 (in) "Address Input", D5 I/O3 (io) "Data Input / Output", D6 VDD (power) "Power", E1 VDD (power) "Power", E4 A16 (in) "Address Input", E5 I/O4 (io) "Data Input / Output", E6 GND (power) "Ground", F3 A14 (in) "Address Input", F4 A15 (in) "Address Input", F5 I/O5 (io) "Data Input / Output", F6 I/O6 (io) "Data Input / Output", G3 A12 (in) "Address Input", G4 A13 (in) "Address Input", G5 ~{WE} (in) "Write Enable Input", G6 I/O7 (io) "Data Input / Output", H1 A18 (in) "Address Input", H2 A8 (in) "Address Input", H3 A9 (in) "Address Input", H4 A10 (in) "Address Input", H5 A11 (in) "Address Input", H6 A19 (in) "Address Input"
part B pins: A1 NC "No Connection", A6 NC "No Connection", B1 NC "No Connection", B2 NC "No Connection", C1 NC "No Connection", C2 NC "No Connection", D2 NC "No Connection", E2 NC "No Connection", E3 NC "No Connection", F1 NC "No Connection", F2 NC "No Connection", G1 NC "No Connection", G2 NC "No Connection"

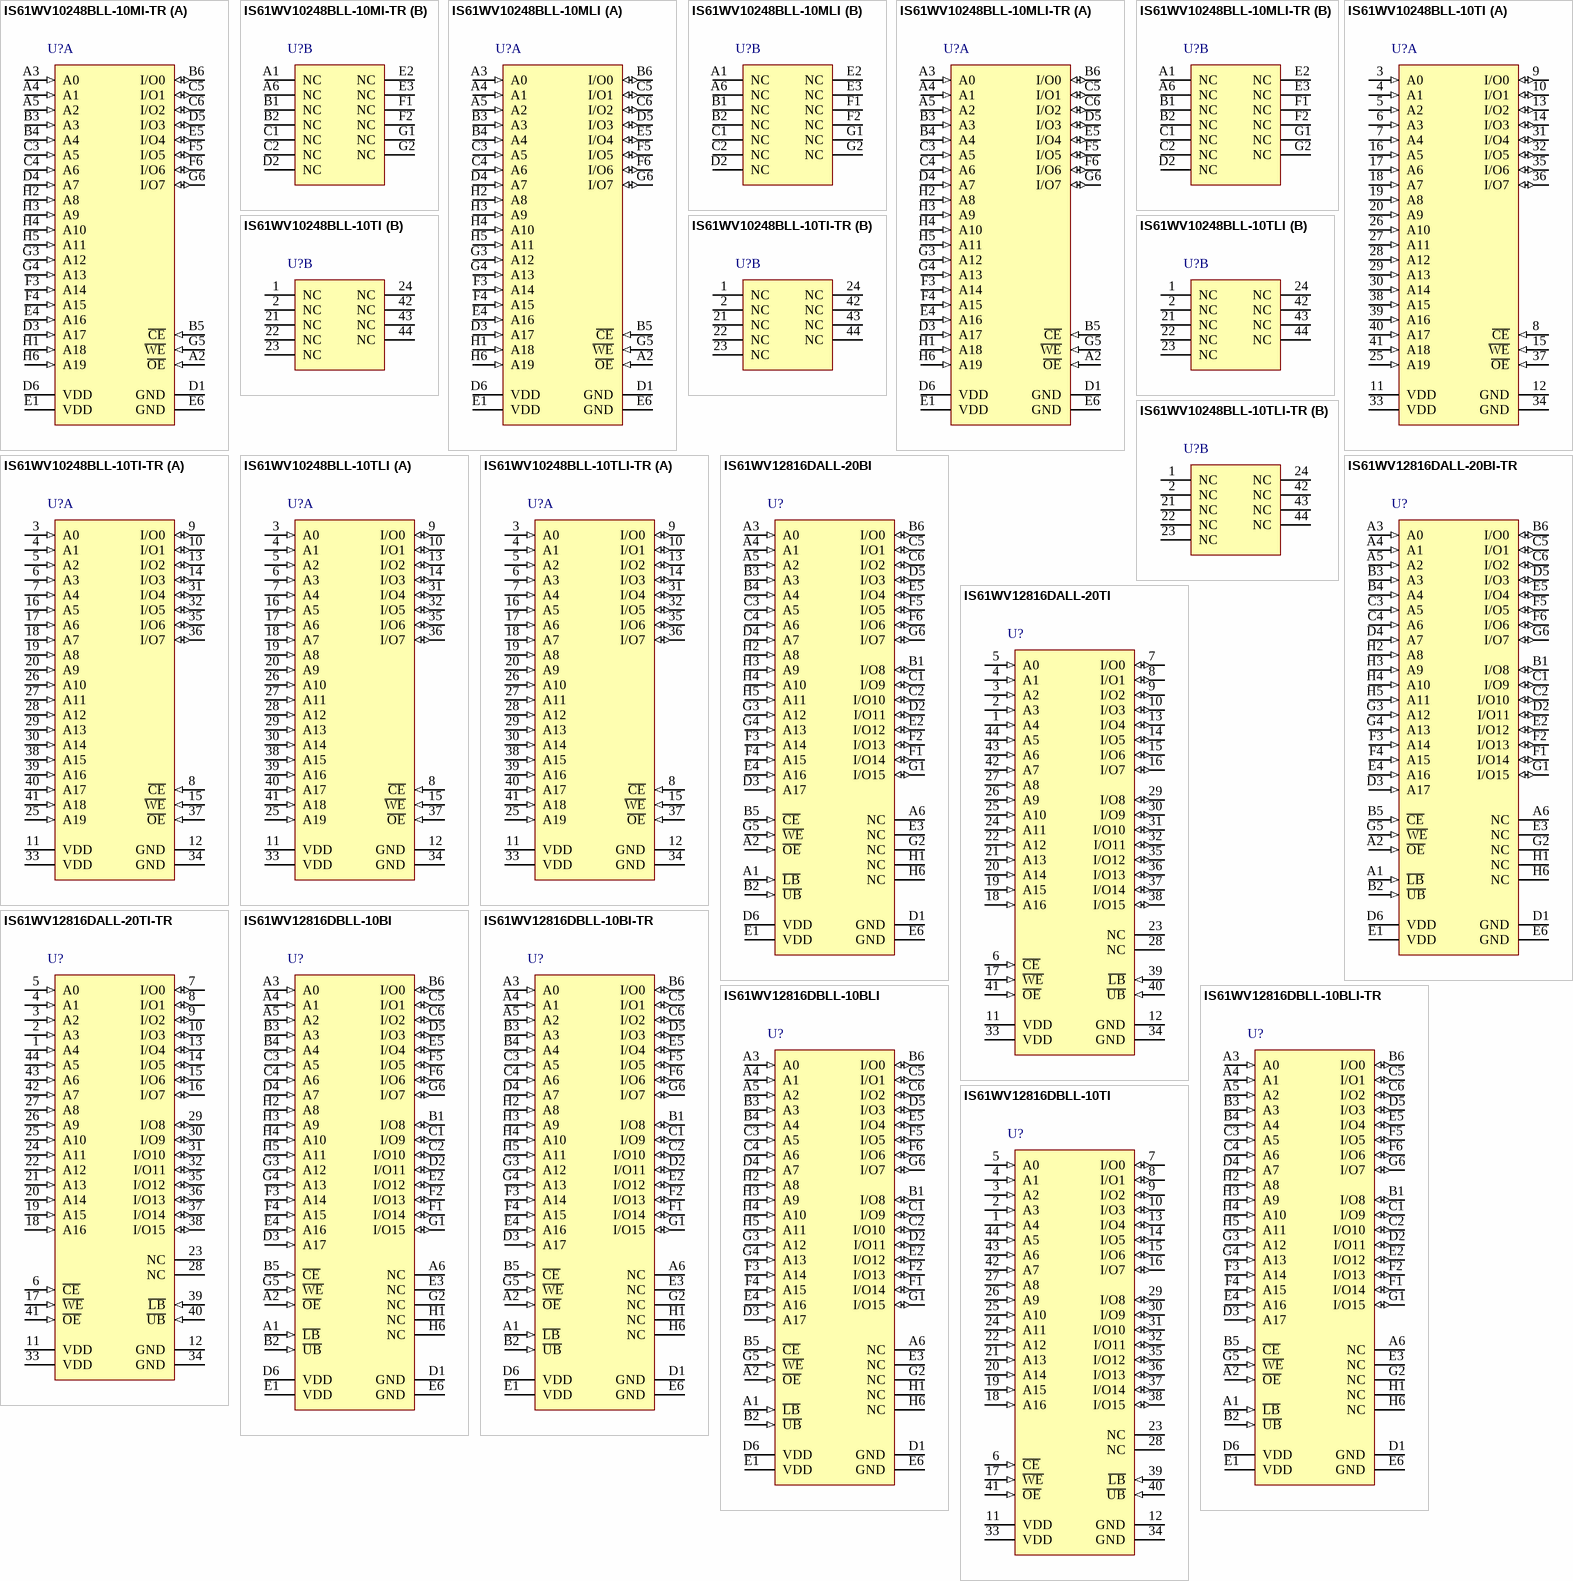
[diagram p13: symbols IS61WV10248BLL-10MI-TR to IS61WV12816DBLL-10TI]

## IS61WV10248BLL-10MI-TR
designator U?
8 M High Speed CMOS SRAM, 1 M x 8, -40 to 85 degC, 48-Pin BGA (TF-BGA-48); Manufacturer: Integrated Silicon Solution Inc (ISSI); PartNumber: IS61WV10248BLL-10MI-TR; Organization: 1M x 8; Packing: Tape & Reel; Speed (ns): 10
footprint ISSI-TF-BGA-48-9000x11000DE (BGA, 48-Balls, Body 11x9mm, Pitch 0.75mm)
part A pins: A2 ~{OE} (in) "Output Enable Input", A3 A0 (in) "Address Input", A4 A1 (in) "Address Input", A5 A2 (in) "Address Input", B3 A3 (in) "Address Input", B4 A4 (in) "Address Input", B5 ~{CE} (in) "Chip Enable Input", B6 I/O0 (io) "Data Input / Output", C3 A5 (in) "Address Input", C4 A6 (in) "Address Input", C5 I/O1 (io) "Data Input / Output", C6 I/O2 (io) "Data Input / Output", D1 GND (power) "Ground", D3 A17 (in) "Address Input", D4 A7 (in) "Address Input", D5 I/O3 (io) "Data Input / Output", D6 VDD (power) "Power", E1 VDD (power) "Power", E4 A16 (in) "Address Input", E5 I/O4 (io) "Data Input / Output", E6 GND (power) "Ground", F3 A14 (in) "Address Input", F4 A15 (in) "Address Input", F5 I/O5 (io) "Data Input / Output", F6 I/O6 (io) "Data Input / Output", G3 A12 (in) "Address Input", G4 A13 (in) "Address Input", G5 ~{WE} (in) "Write Enable Input", G6 I/O7 (io) "Data Input / Output", H1 A18 (in) "Address Input", H2 A8 (in) "Address Input", H3 A9 (in) "Address Input", H4 A10 (in) "Address Input", H5 A11 (in) "Address Input", H6 A19 (in) "Address Input"
part B pins: A1 NC "No Connection", A6 NC "No Connection", B1 NC "No Connection", B2 NC "No Connection", C1 NC "No Connection", C2 NC "No Connection", D2 NC "No Connection", E2 NC "No Connection", E3 NC "No Connection", F1 NC "No Connection", F2 NC "No Connection", G1 NC "No Connection", G2 NC "No Connection"

## IS61WV10248BLL-10MLI
designator U?
8 M High Speed CMOS SRAM, 1 M x 8, -40 to 85 degC, 48-Pin BGA (TF-BGA-48), Pb-Free; Manufacturer: Integrated Silicon Solution Inc (ISSI); PartNumber: IS61WV10248BLL-10MLI; Organization: 1M x 8; Packing: Tray / Tube; Speed (ns): 10
footprint ISSI-TF-BGA-48-9000x11000DE (BGA, 48-Balls, Body 11x9mm, Pitch 0.75mm)
part A pins: A2 ~{OE} (in) "Output Enable Input", A3 A0 (in) "Address Input", A4 A1 (in) "Address Input", A5 A2 (in) "Address Input", B3 A3 (in) "Address Input", B4 A4 (in) "Address Input", B5 ~{CE} (in) "Chip Enable Input", B6 I/O0 (io) "Data Input / Output", C3 A5 (in) "Address Input", C4 A6 (in) "Address Input", C5 I/O1 (io) "Data Input / Output", C6 I/O2 (io) "Data Input / Output", D1 GND (power) "Ground", D3 A17 (in) "Address Input", D4 A7 (in) "Address Input", D5 I/O3 (io) "Data Input / Output", D6 VDD (power) "Power", E1 VDD (power) "Power", E4 A16 (in) "Address Input", E5 I/O4 (io) "Data Input / Output", E6 GND (power) "Ground", F3 A14 (in) "Address Input", F4 A15 (in) "Address Input", F5 I/O5 (io) "Data Input / Output", F6 I/O6 (io) "Data Input / Output", G3 A12 (in) "Address Input", G4 A13 (in) "Address Input", G5 ~{WE} (in) "Write Enable Input", G6 I/O7 (io) "Data Input / Output", H1 A18 (in) "Address Input", H2 A8 (in) "Address Input", H3 A9 (in) "Address Input", H4 A10 (in) "Address Input", H5 A11 (in) "Address Input", H6 A19 (in) "Address Input"
part B pins: A1 NC "No Connection", A6 NC "No Connection", B1 NC "No Connection", B2 NC "No Connection", C1 NC "No Connection", C2 NC "No Connection", D2 NC "No Connection", E2 NC "No Connection", E3 NC "No Connection", F1 NC "No Connection", F2 NC "No Connection", G1 NC "No Connection", G2 NC "No Connection"

## IS61WV10248BLL-10MLI-TR
designator U?
8 M High Speed CMOS SRAM, 1 M x 8, -40 to 85 degC, 48-Pin BGA (TF-BGA-48), Pb-Free; Manufacturer: Integrated Silicon Solution Inc (ISSI); PartNumber: IS61WV10248BLL-10MLI-TR; Organization: 1M x 8; Packing: Tape & Reel; Speed (ns): 10
footprint ISSI-TF-BGA-48-9000x11000DE (BGA, 48-Balls, Body 11x9mm, Pitch 0.75mm)
part A pins: A2 ~{OE} (in) "Output Enable Input", A3 A0 (in) "Address Input", A4 A1 (in) "Address Input", A5 A2 (in) "Address Input", B3 A3 (in) "Address Input", B4 A4 (in) "Address Input", B5 ~{CE} (in) "Chip Enable Input", B6 I/O0 (io) "Data Input / Output", C3 A5 (in) "Address Input", C4 A6 (in) "Address Input", C5 I/O1 (io) "Data Input / Output", C6 I/O2 (io) "Data Input / Output", D1 GND (power) "Ground", D3 A17 (in) "Address Input", D4 A7 (in) "Address Input", D5 I/O3 (io) "Data Input / Output", D6 VDD (power) "Power", E1 VDD (power) "Power", E4 A16 (in) "Address Input", E5 I/O4 (io) "Data Input / Output", E6 GND (power) "Ground", F3 A14 (in) "Address Input", F4 A15 (in) "Address Input", F5 I/O5 (io) "Data Input / Output", F6 I/O6 (io) "Data Input / Output", G3 A12 (in) "Address Input", G4 A13 (in) "Address Input", G5 ~{WE} (in) "Write Enable Input", G6 I/O7 (io) "Data Input / Output", H1 A18 (in) "Address Input", H2 A8 (in) "Address Input", H3 A9 (in) "Address Input", H4 A10 (in) "Address Input", H5 A11 (in) "Address Input", H6 A19 (in) "Address Input"
part B pins: A1 NC "No Connection", A6 NC "No Connection", B1 NC "No Connection", B2 NC "No Connection", C1 NC "No Connection", C2 NC "No Connection", D2 NC "No Connection", E2 NC "No Connection", E3 NC "No Connection", F1 NC "No Connection", F2 NC "No Connection", G1 NC "No Connection", G2 NC "No Connection"

## IS61WV10248BLL-10TI
designator U?
8 M High Speed CMOS SRAM, 1 M x 8, -40 to 85 degC, 44-Pin SOP (TSOP-2-44); Manufacturer: Integrated Silicon Solution Inc (ISSI); PartNumber: IS61WV10248BLL-10TI; Organization: 1M x 8; Packing: Tray / Tube; Speed (ns): 10
footprint ISSI-TSOP-2-44_N (SOP, 44-Leads, Body 18.5x10.3mm, Pitch 0.8mm, IPC Medium Density)
part A pins: 3 A0 (in) "Address Input", 4 A1 (in) "Address Input", 5 A2 (in) "Address Input", 6 A3 (in) "Address Input", 7 A4 (in) "Address Input", 8 ~{CE} (in) "Chip Enable Input", 9 I/O0 (io) "Data Input / Output", 10 I/O1 (io) "Data Input / Output", 11 VDD (power) "Power", 12 GND (power) "Ground", 13 I/O2 (io) "Data Input / Output", 14 I/O3 (io) "Data Input / Output", 15 ~{WE} (in) "Write Enable Input", 16 A5 (in) "Address Input", 17 A6 (in) "Address Input", 18 A7 (in) "Address Input", 19 A8 (in) "Address Input", 20 A9 (in) "Address Input", 25 A19 (in) "Address Input", 26 A10 (in) "Address Input", 27 A11 (in) "Address Input", 28 A12 (in) "Address Input", 29 A13 (in) "Address Input", 30 A14 (in) "Address Input", 31 I/O4 (io) "Data Input / Output", 32 I/O5 (io) "Data Input / Output", 33 VDD (power) "Power", 34 GND (power) "Ground", 35 I/O6 (io) "Data Input / Output", 36 I/O7 (io) "Data Input / Output", 37 ~{OE} (in) "Output Enable Input", 38 A15 (in) "Address Input", 39 A16 (in) "Address Input", 40 A17 (in) "Address Input", 41 A18 (in) "Address Input"
part B pins: 1 NC "No Connection", 2 NC "No Connection", 21 NC "No Connection", 22 NC "No Connection", 23 NC "No Connection", 24 NC "No Connection", 42 NC "No Connection", 43 NC "No Connection", 44 NC "No Connection"

## IS61WV10248BLL-10TI-TR
designator U?
8 M High Speed CMOS SRAM, 1 M x 8, -40 to 85 degC, 44-Pin SOP (TSOP-2-44); Manufacturer: Integrated Silicon Solution Inc (ISSI); PartNumber: IS61WV10248BLL-10TI-TR; Organization: 1M x 8; Packing: Tape & Reel; Speed (ns): 10
footprint ISSI-TSOP-2-44_N (SOP, 44-Leads, Body 18.5x10.3mm, Pitch 0.8mm, IPC Medium Density)
part A pins: 3 A0 (in) "Address Input", 4 A1 (in) "Address Input", 5 A2 (in) "Address Input", 6 A3 (in) "Address Input", 7 A4 (in) "Address Input", 8 ~{CE} (in) "Chip Enable Input", 9 I/O0 (io) "Data Input / Output", 10 I/O1 (io) "Data Input / Output", 11 VDD (power) "Power", 12 GND (power) "Ground", 13 I/O2 (io) "Data Input / Output", 14 I/O3 (io) "Data Input / Output", 15 ~{WE} (in) "Write Enable Input", 16 A5 (in) "Address Input", 17 A6 (in) "Address Input", 18 A7 (in) "Address Input", 19 A8 (in) "Address Input", 20 A9 (in) "Address Input", 25 A19 (in) "Address Input", 26 A10 (in) "Address Input", 27 A11 (in) "Address Input", 28 A12 (in) "Address Input", 29 A13 (in) "Address Input", 30 A14 (in) "Address Input", 31 I/O4 (io) "Data Input / Output", 32 I/O5 (io) "Data Input / Output", 33 VDD (power) "Power", 34 GND (power) "Ground", 35 I/O6 (io) "Data Input / Output", 36 I/O7 (io) "Data Input / Output", 37 ~{OE} (in) "Output Enable Input", 38 A15 (in) "Address Input", 39 A16 (in) "Address Input", 40 A17 (in) "Address Input", 41 A18 (in) "Address Input"
part B pins: 1 NC "No Connection", 2 NC "No Connection", 21 NC "No Connection", 22 NC "No Connection", 23 NC "No Connection", 24 NC "No Connection", 42 NC "No Connection", 43 NC "No Connection", 44 NC "No Connection"

## IS61WV10248BLL-10TLI
designator U?
8 M High Speed CMOS SRAM, 1 M x 8, -40 to 85 degC, 44-Pin SOP (TSOP-2-44), Pb-Free; Manufacturer: Integrated Silicon Solution Inc (ISSI); PartNumber: IS61WV10248BLL-10TLI; Organization: 1M x 8; Packing: Tray / Tube; Speed (ns): 10
footprint ISSI-TSOP-2-44_N (SOP, 44-Leads, Body 18.5x10.3mm, Pitch 0.8mm, IPC Medium Density)
part A pins: 3 A0 (in) "Address Input", 4 A1 (in) "Address Input", 5 A2 (in) "Address Input", 6 A3 (in) "Address Input", 7 A4 (in) "Address Input", 8 ~{CE} (in) "Chip Enable Input", 9 I/O0 (io) "Data Input / Output", 10 I/O1 (io) "Data Input / Output", 11 VDD (power) "Power", 12 GND (power) "Ground", 13 I/O2 (io) "Data Input / Output", 14 I/O3 (io) "Data Input / Output", 15 ~{WE} (in) "Write Enable Input", 16 A5 (in) "Address Input", 17 A6 (in) "Address Input", 18 A7 (in) "Address Input", 19 A8 (in) "Address Input", 20 A9 (in) "Address Input", 25 A19 (in) "Address Input", 26 A10 (in) "Address Input", 27 A11 (in) "Address Input", 28 A12 (in) "Address Input", 29 A13 (in) "Address Input", 30 A14 (in) "Address Input", 31 I/O4 (io) "Data Input / Output", 32 I/O5 (io) "Data Input / Output", 33 VDD (power) "Power", 34 GND (power) "Ground", 35 I/O6 (io) "Data Input / Output", 36 I/O7 (io) "Data Input / Output", 37 ~{OE} (in) "Output Enable Input", 38 A15 (in) "Address Input", 39 A16 (in) "Address Input", 40 A17 (in) "Address Input", 41 A18 (in) "Address Input"
part B pins: 1 NC "No Connection", 2 NC "No Connection", 21 NC "No Connection", 22 NC "No Connection", 23 NC "No Connection", 24 NC "No Connection", 42 NC "No Connection", 43 NC "No Connection", 44 NC "No Connection"

## IS61WV10248BLL-10TLI-TR
designator U?
8 M High Speed CMOS SRAM, 1 M x 8, -40 to 85 degC, 44-Pin SOP (TSOP-2-44), Pb-Free; Manufacturer: Integrated Silicon Solution Inc (ISSI); PartNumber: IS61WV10248BLL-10TLI-TR; Organization: 1M x 8; Packing: Tape & Reel; Speed (ns): 10
footprint ISSI-TSOP-2-44_N (SOP, 44-Leads, Body 18.5x10.3mm, Pitch 0.8mm, IPC Medium Density)
part A pins: 3 A0 (in) "Address Input", 4 A1 (in) "Address Input", 5 A2 (in) "Address Input", 6 A3 (in) "Address Input", 7 A4 (in) "Address Input", 8 ~{CE} (in) "Chip Enable Input", 9 I/O0 (io) "Data Input / Output", 10 I/O1 (io) "Data Input / Output", 11 VDD (power) "Power", 12 GND (power) "Ground", 13 I/O2 (io) "Data Input / Output", 14 I/O3 (io) "Data Input / Output", 15 ~{WE} (in) "Write Enable Input", 16 A5 (in) "Address Input", 17 A6 (in) "Address Input", 18 A7 (in) "Address Input", 19 A8 (in) "Address Input", 20 A9 (in) "Address Input", 25 A19 (in) "Address Input", 26 A10 (in) "Address Input", 27 A11 (in) "Address Input", 28 A12 (in) "Address Input", 29 A13 (in) "Address Input", 30 A14 (in) "Address Input", 31 I/O4 (io) "Data Input / Output", 32 I/O5 (io) "Data Input / Output", 33 VDD (power) "Power", 34 GND (power) "Ground", 35 I/O6 (io) "Data Input / Output", 36 I/O7 (io) "Data Input / Output", 37 ~{OE} (in) "Output Enable Input", 38 A15 (in) "Address Input", 39 A16 (in) "Address Input", 40 A17 (in) "Address Input", 41 A18 (in) "Address Input"
part B pins: 1 NC "No Connection", 2 NC "No Connection", 21 NC "No Connection", 22 NC "No Connection", 23 NC "No Connection", 24 NC "No Connection", 42 NC "No Connection", 43 NC "No Connection", 44 NC "No Connection"

## IS61WV12816DALL-20BI
designator U?
2 M High Speed Asynchronous CMOS SRAM, 128 K x 16, -40 to 85 degC, 48-Pin BGA (TF-BGA-48); Manufacturer: Integrated Silicon Solution Inc (ISSI); PartNumber: IS61WV12816DALL-20BI; Packing: Tray / Tube; Speed (ns): 20
footprint ISSI-TF-BGA-48-6000X8000DE (BGA, 48-Balls, Body 8x6mm, Pitch 0.75mm)
pins: A1 ~{LB} (in) "Lower-byte Control (I/O0-I/O7)", A2 ~{OE} (in) "Output Enable Input", A3 A0 (in) "Address Input", A4 A1 (in) "Address Input", A5 A2 (in) "Address Input", A6 NC "No Connection", B1 I/O8 (io) "Data Input/Output", B2 ~{UB} (in) "Upper-byte Control (I/O8-I/O15)", B3 A3 (in) "Address Input", B4 A4 (in) "Address Input", B5 ~{CE} (in) "Chip Enable Input", B6 I/O0 (io) "Data Input/Output", C1 I/O9 (io) "Data Input/Output", C2 I/O10 (io) "Data Input/Output", C3 A5 (in) "Address Input", C4 A6 (in) "Address Input", C5 I/O1 (io) "Data Input/Output", C6 I/O2 (io) "Data Input/Output", D1 GND (power) "Ground", D2 I/O11 (io) "Data Input/Output", D3 A17 (in) "Address Input", D4 A7 (in) "Address Input", D5 I/O3 (io) "Data Input/Output", D6 VDD (power) "Power", E1 VDD (power) "Power", E2 I/O12 (io) "Data Input/Output", E3 NC "No Connection", E4 A16 (in) "Address Input", E5 I/O4 (io) "Data Input/Output", E6 GND (power) "Ground", F1 I/O14 (io) "Data Input/Output", F2 I/O13 (io) "Data Input/Output", F3 A14 (in) "Address Input", F4 A15 (in) "Address Input", F5 I/O5 (io) "Data Input/Output", F6 I/O6 (io) "Data Input/Output", G1 I/O15 (io) "Data Input/Output", G2 NC "No Connection", G3 A12 (in) "Address Input", G4 A13 (in) "Address Input", G5 ~{WE} (in) "Write Enable Input", G6 I/O7 (io) "Data Input/Output", H1 NC "No Connection", H2 A8 (in) "Address Input", H3 A9 (in) "Address Input", H4 A10 (in) "Address Input", H5 A11 (in) "Address Input", H6 NC "No Connection"

## IS61WV12816DALL-20BI-TR
designator U?
2 M High Speed Asynchronous CMOS SRAM, 128 K x 16, -40 to 85 degC, 48-Pin BGA (TF-BGA-48); Manufacturer: Integrated Silicon Solution Inc (ISSI); PartNumber: IS61WV12816DALL-20BI-TR; Packing: Tape & Reel; Speed (ns): 20
footprint ISSI-TF-BGA-48-6000X8000DE (BGA, 48-Balls, Body 8x6mm, Pitch 0.75mm)
pins: A1 ~{LB} (in) "Lower-byte Control (I/O0-I/O7)", A2 ~{OE} (in) "Output Enable Input", A3 A0 (in) "Address Input", A4 A1 (in) "Address Input", A5 A2 (in) "Address Input", A6 NC "No Connection", B1 I/O8 (io) "Data Input/Output", B2 ~{UB} (in) "Upper-byte Control (I/O8-I/O15)", B3 A3 (in) "Address Input", B4 A4 (in) "Address Input", B5 ~{CE} (in) "Chip Enable Input", B6 I/O0 (io) "Data Input/Output", C1 I/O9 (io) "Data Input/Output", C2 I/O10 (io) "Data Input/Output", C3 A5 (in) "Address Input", C4 A6 (in) "Address Input", C5 I/O1 (io) "Data Input/Output", C6 I/O2 (io) "Data Input/Output", D1 GND (power) "Ground", D2 I/O11 (io) "Data Input/Output", D3 A17 (in) "Address Input", D4 A7 (in) "Address Input", D5 I/O3 (io) "Data Input/Output", D6 VDD (power) "Power", E1 VDD (power) "Power", E2 I/O12 (io) "Data Input/Output", E3 NC "No Connection", E4 A16 (in) "Address Input", E5 I/O4 (io) "Data Input/Output", E6 GND (power) "Ground", F1 I/O14 (io) "Data Input/Output", F2 I/O13 (io) "Data Input/Output", F3 A14 (in) "Address Input", F4 A15 (in) "Address Input", F5 I/O5 (io) "Data Input/Output", F6 I/O6 (io) "Data Input/Output", G1 I/O15 (io) "Data Input/Output", G2 NC "No Connection", G3 A12 (in) "Address Input", G4 A13 (in) "Address Input", G5 ~{WE} (in) "Write Enable Input", G6 I/O7 (io) "Data Input/Output", H1 NC "No Connection", H2 A8 (in) "Address Input", H3 A9 (in) "Address Input", H4 A10 (in) "Address Input", H5 A11 (in) "Address Input", H6 NC "No Connection"

## IS61WV12816DALL-20TI
designator U?
2 M High Speed Asynchronous CMOS SRAM, 128 K x 16, -40 to 85 degC, 44-Pin SOP (TSOP-2-44); Manufacturer: Integrated Silicon Solution Inc (ISSI); PartNumber: IS61WV12816DALL-20TI; Packing: Tray / Tube; Speed (ns): 20
footprint ISSI-TSOP-2-44_N (SOP, 44-Leads, Body 18.5x10.3mm, Pitch 0.8mm, IPC Medium Density)
pins: 1 A4 (in) "Address Input", 2 A3 (in) "Address Input", 3 A2 (in) "Address Input", 4 A1 (in) "Address Input", 5 A0 (in) "Address Input", 6 ~{CE} (in) "Chip Enable Input", 7 I/O0 (io) "Data Input/Output", 8 I/O1 (io) "Data Input/Output", 9 I/O2 (io) "Data Input/Output", 10 I/O3 (io) "Data Input/Output", 11 VDD (power) "Power", 12 GND (power) "Ground", 13 I/O4 (io) "Data Input/Output", 14 I/O5 (io) "Data Input/Output", 15 I/O6 (io) "Data Input/Output", 16 I/O7 (io) "Data Input/Output", 17 ~{WE} (in) "Write Enable Input", 18 A16 (in) "Address Input", 19 A15 (in) "Address Input", 20 A14 (in) "Address Input", 21 A13 (in) "Address Input", 22 A12 (in) "Address Input", 23 NC "No Connection", 24 A11 (in) "Address Input", 25 A10 (in) "Address Input", 26 A9 (in) "Address Input", 27 A8 (in) "Address Input", 28 NC "No Connection", 29 I/O8 (io) "Data Input/Output", 30 I/O9 (io) "Data Input/Output", 31 I/O10 (io) "Data Input/Output", 32 I/O11 (io) "Data Input/Output", 33 VDD (power) "Power", 34 GND (power) "Ground", 35 I/O12 (io) "Data Input/Output", 36 I/O13 (io) "Data Input/Output", 37 I/O14 (io) "Data Input/Output", 38 I/O15 (io) "Data Input/Output", 39 ~{LB} (in) "Lower-byte Control (I/O0-I/O7)", 40 ~{UB} (in) "Upper-byte Control (I/O8-I/O15)", 41 ~{OE} (in) "Output Enable Input", 42 A7 (in) "Address Input", 43 A6 (in) "Address Input", 44 A5 (in) "Address Input"

## IS61WV12816DALL-20TI-TR
designator U?
2 M High Speed Asynchronous CMOS SRAM, 128 K x 16, -40 to 85 degC, 44-Pin SOP (TSOP-2-44); Manufacturer: Integrated Silicon Solution Inc (ISSI); PartNumber: IS61WV12816DALL-20TI-TR; Packing: Tape & Reel; Speed (ns): 20
footprint ISSI-TSOP-2-44_N (SOP, 44-Leads, Body 18.5x10.3mm, Pitch 0.8mm, IPC Medium Density)
pins: 1 A4 (in) "Address Input", 2 A3 (in) "Address Input", 3 A2 (in) "Address Input", 4 A1 (in) "Address Input", 5 A0 (in) "Address Input", 6 ~{CE} (in) "Chip Enable Input", 7 I/O0 (io) "Data Input/Output", 8 I/O1 (io) "Data Input/Output", 9 I/O2 (io) "Data Input/Output", 10 I/O3 (io) "Data Input/Output", 11 VDD (power) "Power", 12 GND (power) "Ground", 13 I/O4 (io) "Data Input/Output", 14 I/O5 (io) "Data Input/Output", 15 I/O6 (io) "Data Input/Output", 16 I/O7 (io) "Data Input/Output", 17 ~{WE} (in) "Write Enable Input", 18 A16 (in) "Address Input", 19 A15 (in) "Address Input", 20 A14 (in) "Address Input", 21 A13 (in) "Address Input", 22 A12 (in) "Address Input", 23 NC "No Connection", 24 A11 (in) "Address Input", 25 A10 (in) "Address Input", 26 A9 (in) "Address Input", 27 A8 (in) "Address Input", 28 NC "No Connection", 29 I/O8 (io) "Data Input/Output", 30 I/O9 (io) "Data Input/Output", 31 I/O10 (io) "Data Input/Output", 32 I/O11 (io) "Data Input/Output", 33 VDD (power) "Power", 34 GND (power) "Ground", 35 I/O12 (io) "Data Input/Output", 36 I/O13 (io) "Data Input/Output", 37 I/O14 (io) "Data Input/Output", 38 I/O15 (io) "Data Input/Output", 39 ~{LB} (in) "Lower-byte Control (I/O0-I/O7)", 40 ~{UB} (in) "Upper-byte Control (I/O8-I/O15)", 41 ~{OE} (in) "Output Enable Input", 42 A7 (in) "Address Input", 43 A6 (in) "Address Input", 44 A5 (in) "Address Input"

## IS61WV12816DBLL-10BI
designator U?
2 M High Speed Asynchronous CMOS SRAM, 128 K x 16, -40 to 85 degC, 48-Pin BGA (TF-BGA-48); Manufacturer: Integrated Silicon Solution Inc (ISSI); PartNumber: IS61WV12816DBLL-10BI; Packing: Tray / Tube; Speed (ns): 10
footprint ISSI-TF-BGA-48-6000X8000DE (BGA, 48-Balls, Body 8x6mm, Pitch 0.75mm)
pins: A1 ~{LB} (in) "Lower-byte Control (I/O0-I/O7)", A2 ~{OE} (in) "Output Enable Input", A3 A0 (in) "Address Input", A4 A1 (in) "Address Input", A5 A2 (in) "Address Input", A6 NC "No Connection", B1 I/O8 (io) "Data Input/Output", B2 ~{UB} (in) "Upper-byte Control (I/O8-I/O15)", B3 A3 (in) "Address Input", B4 A4 (in) "Address Input", B5 ~{CE} (in) "Chip Enable Input", B6 I/O0 (io) "Data Input/Output", C1 I/O9 (io) "Data Input/Output", C2 I/O10 (io) "Data Input/Output", C3 A5 (in) "Address Input", C4 A6 (in) "Address Input", C5 I/O1 (io) "Data Input/Output", C6 I/O2 (io) "Data Input/Output", D1 GND (power) "Ground", D2 I/O11 (io) "Data Input/Output", D3 A17 (in) "Address Input", D4 A7 (in) "Address Input", D5 I/O3 (io) "Data Input/Output", D6 VDD (power) "Power", E1 VDD (power) "Power", E2 I/O12 (io) "Data Input/Output", E3 NC "No Connection", E4 A16 (in) "Address Input", E5 I/O4 (io) "Data Input/Output", E6 GND (power) "Ground", F1 I/O14 (io) "Data Input/Output", F2 I/O13 (io) "Data Input/Output", F3 A14 (in) "Address Input", F4 A15 (in) "Address Input", F5 I/O5 (io) "Data Input/Output", F6 I/O6 (io) "Data Input/Output", G1 I/O15 (io) "Data Input/Output", G2 NC "No Connection", G3 A12 (in) "Address Input", G4 A13 (in) "Address Input", G5 ~{WE} (in) "Write Enable Input", G6 I/O7 (io) "Data Input/Output", H1 NC "No Connection", H2 A8 (in) "Address Input", H3 A9 (in) "Address Input", H4 A10 (in) "Address Input", H5 A11 (in) "Address Input", H6 NC "No Connection"

## IS61WV12816DBLL-10BI-TR
designator U?
2 M High Speed Asynchronous CMOS SRAM, 128 K x 16, -40 to 85 degC, 48-Pin BGA (TF-BGA-48); Manufacturer: Integrated Silicon Solution Inc (ISSI); PartNumber: IS61WV12816DBLL-10BI-TR; Packing: Tape & Reel; Speed (ns): 10
footprint ISSI-TF-BGA-48-6000X8000DE (BGA, 48-Balls, Body 8x6mm, Pitch 0.75mm)
pins: A1 ~{LB} (in) "Lower-byte Control (I/O0-I/O7)", A2 ~{OE} (in) "Output Enable Input", A3 A0 (in) "Address Input", A4 A1 (in) "Address Input", A5 A2 (in) "Address Input", A6 NC "No Connection", B1 I/O8 (io) "Data Input/Output", B2 ~{UB} (in) "Upper-byte Control (I/O8-I/O15)", B3 A3 (in) "Address Input", B4 A4 (in) "Address Input", B5 ~{CE} (in) "Chip Enable Input", B6 I/O0 (io) "Data Input/Output", C1 I/O9 (io) "Data Input/Output", C2 I/O10 (io) "Data Input/Output", C3 A5 (in) "Address Input", C4 A6 (in) "Address Input", C5 I/O1 (io) "Data Input/Output", C6 I/O2 (io) "Data Input/Output", D1 GND (power) "Ground", D2 I/O11 (io) "Data Input/Output", D3 A17 (in) "Address Input", D4 A7 (in) "Address Input", D5 I/O3 (io) "Data Input/Output", D6 VDD (power) "Power", E1 VDD (power) "Power", E2 I/O12 (io) "Data Input/Output", E3 NC "No Connection", E4 A16 (in) "Address Input", E5 I/O4 (io) "Data Input/Output", E6 GND (power) "Ground", F1 I/O14 (io) "Data Input/Output", F2 I/O13 (io) "Data Input/Output", F3 A14 (in) "Address Input", F4 A15 (in) "Address Input", F5 I/O5 (io) "Data Input/Output", F6 I/O6 (io) "Data Input/Output", G1 I/O15 (io) "Data Input/Output", G2 NC "No Connection", G3 A12 (in) "Address Input", G4 A13 (in) "Address Input", G5 ~{WE} (in) "Write Enable Input", G6 I/O7 (io) "Data Input/Output", H1 NC "No Connection", H2 A8 (in) "Address Input", H3 A9 (in) "Address Input", H4 A10 (in) "Address Input", H5 A11 (in) "Address Input", H6 NC "No Connection"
